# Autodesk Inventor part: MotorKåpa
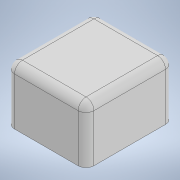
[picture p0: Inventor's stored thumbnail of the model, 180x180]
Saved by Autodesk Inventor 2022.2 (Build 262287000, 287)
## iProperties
Created: 2022-03
Part Number: MotorKåpa
Material: Generic
Document SubType Name: Modeling
Designer: cl
Density: 1 g/cm^3
Appearance: Default
Author: cl
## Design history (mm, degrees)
sketch "Sketch1"
  geometry: L1 (-10, 0)-(-90, 0); L2 (-100, -10)-(-100, -100); L3 (-90, -110)-(-10, -110); L4 (0, -100)-(0, -10); A1 r 10 centre (-10, -10) between (0, -10) and (-10, 0); A2 r 10 centre (-10, -100) between (-10, -110) and (0, -100); A3 r 10 centre (-90, -100) between (-100, -100) and (-90, -110); A4 r 10 centre (-90, -10) between (-90, 0) and (-100, -10); 4 further points
  constraints: 8 end point, 8 point on circle, 8 point on line, 8 tangent, 4 centre point, 3 equal radius, 2 parallel, 1 horizontal, 1 perpendicular
  dimensions: "d0" = 100 distance of point (0, -110) point (-100, -110); "d1" = 110 distance of point (-100, -110) point (-100, 0); "d2" = 10 radius of A1
extrude "Extrusion1" new body sketch "Sketch1" distance "d3" = 70; taper "d4" = 0 deg
fillet "Fillet1" dims "d5" = 10
body "Solid1"
